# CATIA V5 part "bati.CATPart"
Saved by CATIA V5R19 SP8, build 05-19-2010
Part number: bati
Bounding box of the stored display mesh (mm): x -100 to 100, y 0 to 300, z 0 to 610
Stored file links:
  C:\Users\ThinkMotion\Desktop\EU_thinkMotion\iao\IAO_MMS_Groupe3\avercruysse\IAO_vercruysse\IAO_vercruysse\bati.CATPart
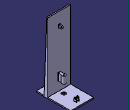
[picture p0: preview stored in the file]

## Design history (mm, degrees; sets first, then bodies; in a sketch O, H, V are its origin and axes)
Body1 (main body)
  Sketch1 on yz-plane, origin (0, 0, 0), H (0, 1, 0), V (0, 0, 1)
    line L1 (300, 10) -> (100, 10)
    line L2 (100, 10) -> (100, 610)
    line L3 (100, 610) -> (90, 610)
    point P5 (0, 0)
    line L4 (0, 0) -> (300, 0)
    line L5 (300, 0) -> (300, 10)
    line L6 (0, 0) -> (0, 10)
    point P7 (0, 10)
    line L7 (0, 10) -> (69.0475, 10)
    line L8 (69.0475, 10) -> (90, 610)
    reference intersected line E1 through (0, 0) direction (0, 1) from zx-plane
    reference intersected line E2 through (0, 0) direction (-1, 0) from xy-plane
    distance E1 L5 = 300
    length L5 = 10
    length L4 = 300
    length L1 = 200
    angle L7 L8 = 92
    length L2 = 600
    length L3 = 10
    horizontal: L1 H, L3 H, L4 H, L7 H
    vertical: L2 V, L5 V, L6 V
    coincidence: P7 L1, P5 E2
  Pad1: profile Sketch1, direction (1, 0, 0), length 100, opposite side length 100
  Sketch2 on face of Pad1 from Sketch1.L1, origin (0, 0, 10), H (1, 0, 0), V (0, 1, 0)
    point P1 (0, 250)
    line L1 (12, 262.5) -> (12, 237.5)
    line L2 (12, 237.5) -> (-12, 237.5)
    line L3 (-12, 237.5) -> (-12, 262.5)
    line L4 (-12, 262.5) -> (12, 262.5)
    reference intersected line E1 through (0, 0) direction (0, 1) from yz-plane
    reference intersected line E2 through (0, 0) direction (-1, 0) from zx-plane
    length L4 = 24
    length L1 = 25
    distance P1 E2 = 250
    vertical: L1 V, L3 V
    horizontal: L2 H, L4 H
    equidistance: L1 L3 P1, L2 L4 P1
    coincidence: P1 E1
  Sketch3 on yz-plane, origin (0, 0, 0), H (0, 1, 0), V (0, 0, 1)
    arc A1 centre (250, 31) radius 10 from (259.9335, 32.1509) to (240.0665, 32.1509) ccw
    point P1 (250, 31)
    point P2 (262.5, 10)
    line L1 (262.5, 10) -> (259.9335, 32.1509)
    point P3 (237.5, 10)
    line L2 (237.5, 10) -> (240.0665, 32.1509)
    line L3 (237.5, 10) -> (262.5, 10)
    reference projected point E1 (262.5, 10) from vertex [element of Sketch2 | element of Sketch2]
    reference projected point E2 (237.5, 10) from vertex [element of Sketch2 | element of Sketch2]
    reference projected point E3 (262.5, 10) from vertex [element of Sketch2 | element of Sketch2]
    reference projected line E4 (300, 10) -> (-360, 10) from edge [face of Pad1 from Sketch1.L1 | end face of Pad1]
    distance E3 P1 H = 12.5
    distance P1 E4 = 21
    radius A1 = 10
    tangency: L1 A1, L2 A1
    horizontal: L3 H
    coincidence: E1 P2, E2 P3
  SolidCombine1: FirstComponentProfile Sketch2, FirstComponentDirection Sketch2, SecondComponentProfile Sketch3, SecondComponentDirection Sketch3
  Sketch4 on face of Pad1 from Sketch1.L5, origin (0, 300, 0), H (-1, 0, 0), V (0, 0, 1)
    point P1 (0, 50)
    line L1 (8, 90) -> (8, 10)
    line L2 (8, 10) -> (-8, 10)
    line L3 (-8, 10) -> (-8, 90)
    line L4 (-8, 90) -> (8, 90)
    reference projected line E1 (100, 10) -> (-100, 10) from edge [face of Pad1 from Sketch1.L1 | face of Pad1 from Sketch1.L5]
    length L4 = 16
    length L1 = 80
    coincidence: P1 V, E1 L2
    vertical: L1 V, L3 V
    horizontal: L2 H, L4 H
    equidistance: L1 L3 P1, L2 L4 P1
  Pocket1: profile Sketch4, direction (0, -1, 0), up to face of SolidCombine1 from Sketch3.L2
  Sketch5 on face of SolidCombine1 from Sketch2.L3, origin (-12, 0, 0), H (0, -1, 0), V (0, 0, 1)
    circle A1 centre (-250, 31) radius 5
    point P1 (-250, 31)
    reference projected arc E1 centre (-250, 31) radius 10 from (-240.1308, 32.6122) to (-259.8692, 32.6122) ccw from edge [face of SolidCombine1 from Sketch2.L3 | face of SolidCombine1 from Sketch3.A1]
    radius A1 = 5
    concentricity: P1 E1
  Pocket2: profile Sketch5, direction (1, 0, 0), through (limit type 3)
  Sketch6 on face of Pad1 from Sketch1.L2, origin (0, 100, 0), H (-1, 0, 0), V (0, 0, 1)
    point P1 (0, 500)
    line L1 (5, 512.5) -> (5, 487.5)
    line L2 (5, 487.5) -> (-5, 487.5)
    line L3 (-5, 487.5) -> (-5, 512.5)
    line L4 (-5, 512.5) -> (5, 512.5)
    reference projected point E1 (0, 512.5) from vertex [element of Sketch7 | element of Sketch7]
    reference projected point E2 (0, 487.5) from vertex [element of Sketch7 | element of Sketch7]
    length L4 = 10
    coincidence: P1 V, E1 L4, E2 L2
    vertical: L1 V, L3 V
    horizontal: L2 H, L4 H
    equidistance: L1 L3 P1, L2 L4 P1
  Sketch7 on yz-plane, origin (0, 0, 0), H (0, 1, 0), V (0, 0, 1)
    axis line L1 (-224.6314, 500) -> (207.8869, 500)
    point P2 (207.8869, 500)
    arc A1 centre (121, 500) radius 10 from (122.1509, 490.0665) to (122.1509, 509.9335) ccw
    point P3 (121, 500)
    line L2 (100, 487.5) -> (100, 512.5)
    point P4 (100, 487.5)
    line L3 (100, 512.5) -> (122.1509, 509.9335)
    reference projected line E1 (100, 50) -> (100, 650) from edge [face of Pad1 from Sketch1.L2 | end face of Pad1]
    line L4 (100, 487.5) -> (122.1509, 490.0665)
    reference intersected line E2 through (0, 0) direction (-1, 0) from xy-plane
    distance L1 P4 = 12.5
    length L2 = 25
    distance P3 L2 = 21
    radius A1 = 10
    distance L1 E2 = 500
    horizontal: L1 H
    coincidence: P3 L1, L2 E1, L4 P2
    vertical: L2 V
    tangency: L3 A1, L4 A1
  SolidCombine2: FirstComponentProfile Sketch6, FirstComponentDirection Sketch6, SecondComponentProfile Sketch7, SecondComponentDirection Sketch7
  Sketch8 on face of SolidCombine2 from Sketch6.L1, origin (-5, -184.9687, 497.2769), H (0, 1, 0), V (0, 0, -1)
    point P1 (305.9687, -2.7231)
    reference projected arc E1 centre (305.9687, -2.7231) radius 10 from (307.1196, -12.6567) to (307.1196, 7.2104) ccw from edge [face of SolidCombine2 from Sketch6.L1 | face of SolidCombine2 from Sketch7.A1]
    concentricity: P1 E1
  Hole1: placed by Sketch8, at (-5, 121, 500) direction (1, 0, 0), diameter 8, through (limit type 3)
  Plane1: type Offset, RefPlane xy-plane, Offset 120
  Sketch9 on Plane1, origin (0, 0, 120), H (1, 0, 0), V (0, 1, 0)
    arc A1 centre (0, 140) radius 15 from (12, 131) to (-12, 131) ccw
    point P1 (0, 140)
    line L1 (-10, 125) -> (-10, 100)
    line L2 (-10, 100) -> (10, 100)
    line L3 (10, 100) -> (10, 125)
    axis line L4 (0, -211.6159) -> (0, -102.1198)
    point P4 (0, -211.6159)
    reference projected line E1 (-100, 100) -> (100, 100) from edge [face of Pad1 from Sketch1.L3 | face of Pad1 from Sketch1.L2]
    reference intersected line E2 through (0, 0) direction (0, 1) from yz-plane
    arc A2 centre (20, 125) radius 10 from (12, 131) to (10, 125) ccw
    arc A3 centre (-20, 125) radius 10 from (-12, 131) to (-10, 125) cw
    distance E2 L3 = 10
    length L2 = 20
    distance P1 L2 = 40
    radius A1 = 15
    radius A2 = 10
    radius A3 = 10
    coincidence: P1 V, P4 V, L2 E1
    vertical: L1 V, L3 V, L4 V
    horizontal: L2 H
    tangency: A2 L3, A2 A1, A3 L1, A3 A1
  Sketch10 on yz-plane, origin (0, 0, 0), H (0, 1, 0), V (0, 0, 1)
    point P1 (130, 120)
    line L1 (160, 150) -> (160, 90)
    line L2 (160, 90) -> (100, 90)
    line L3 (100, 90) -> (100, 150)
    line L4 (100, 150) -> (160, 150)
    reference projected line E1 (100, 50) -> (100, 650) from edge [face of Pad1 from Sketch1.L2 | end face of Pad1]
    reference projected line E2 (-162.3607, 120) -> (-200, 120) from Sketch9.L1
    length L2 = 60
    length L1 = 60
    vertical: L1 V, L3 V
    horizontal: L2 H, L4 H
    equidistance: L1 L3 P1, L2 L4 P1
    coincidence: E1 L3, P1 E2
  SolidCombine3: FirstComponentProfile Sketch9, FirstComponentDirection Sketch9, SecondComponentProfile Sketch10, SecondComponentDirection Sketch10
  Sketch11 on face of SolidCombine3 from Sketch10.L4, origin (1.9436, -138.0898, 150), H (1, 0, 0), V (0, 1, 0)
    point P1 (-1.9436, 278.0898)
    reference projected arc E1 centre (-1.9436, 278.0898) radius 15 from (8.0564, 266.9095) to (-11.9436, 266.9095) ccw from edge [face of SolidCombine3 from Sketch10.L4 | face of SolidCombine3 from Sketch9.A1]
    concentricity: E1 P1
  Hole2: placed by Sketch11, at (0, 140, 150) direction (0, 0, -1), diameter 10, through (limit type 3)
  Sketch12 on xy-plane, origin (0, 0, 0), H (1, 0, 0), V (0, 1, 0)
    point P1 (0, 140)
    line L1 (15, 150) -> (15, 130)
    line L2 (10, 125) -> (-10, 125)
    line L3 (-15, 130) -> (-15, 150)
    line L4 (-10, 155) -> (10, 155)
    point P2 (15, 155)
    point P3 (-15, 125)
    point P4 (-15, 155)
    reference projected circle E1 centre (0, 140) radius 5 from edge [face of Pad1 from Sketch1.L4 | face of Hole2]
    arc A1 centre (10, 130) radius 5 from (15, 130) to (10, 125) cw
    arc A2 centre (10, 150) radius 5 from (15, 150) to (10, 155) ccw
    arc A3 centre (-10, 150) radius 5 from (-15, 150) to (-10, 155) cw
    arc A4 centre (-10, 130) radius 5 from (-10, 125) to (-15, 130) cw
    radius A1 = 5
    distance P4 P2 = 30
    radius A2 = 5
    distance P3 P4 = 30
    radius A3 = 5
    radius A4 = 5
    coincidence: P1 V, L1 P2, L4 P2, L3 P4, L4 P4, L2 P3, L3 P3
    vertical: L1 V, L3 V
    horizontal: L2 H, L4 H
    equidistance: L1 L3 P1, L2 L4 P1
    concentricity: P1 E1
    tangency: A1 L1, A1 L2, A2 L1, A2 L4, A3 L3, A3 L4, A4 L2, A4 L3
  Pocket3: profile Sketch12, direction (0, 0, -1), up to face of Pad1
  Chamfer1: length 2, angle 45, on edge [face of SolidCombine3 from Sketch9.L3 | face of Pad1 from Sketch1.L2]; edge [face of Pad1 from Sketch1.L2 | face of SolidCombine3 from Sketch10.L4]; edge [face of SolidCombine1 from Sketch2.L1 | face of Pad1]; edge [face of Pocket1 from Sketch4.L1 | face of Pad1]; edge [face of SolidCombine1 from Sketch3.L1 | face of Pad1] (x2); edge [face of SolidCombine1 from Sketch2.L3 | face of Pad1]; edge [face of Pad1 | face of Pocket1 from Sketch4.L3]; edge [face of Pad1 | face of SolidCombine1 from Sketch3.L2] (x2); edge [face of Pad1 from Sketch1.L2 | face of SolidCombine3 from Sketch9.L1]; edge [face of SolidCombine3 from Sketch10.L2 | face of Pad1 from Sketch1.L2]; edge [face of SolidCombine2 from Sketch6.L1 | face of Pad1 from Sketch1.L2]; edge [face of SolidCombine2 from Sketch7.L4 | face of Pad1 from Sketch1.L2]; edge [face of SolidCombine2 from Sketch6.L3 | face of Pad1 from Sketch1.L2]; edge [face of Pad1 from Sketch1.L2 | face of SolidCombine2 from Sketch7.L3]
